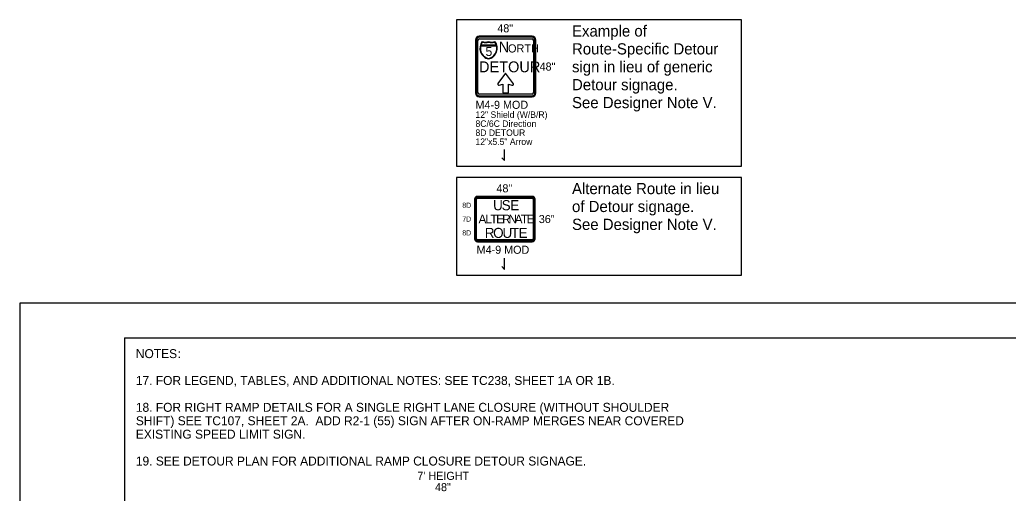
# Model space of a CAD drawing. Extents: x 99999 to 100116, y 99995 to 100013.
# Drawn here: x 100039.06 to 100047.9, y 100008.99 to 100013.22 of the extents above; entities that cross this region are included whole.
import ezdxf

# ---------------------------------------------------------------- set-up
doc = ezdxf.new("R2010")
doc.units = 0
for name, color, linetype in [('SH_GI_GeneralNotesBodyText', 7, 'Continuous'), ('SH_GI_PlotLimits', 7, 'Continuous'), ('SH_GI_SheetBorder', 7, 'Continuous'), ('TR_SN_ConstructionSigns', 7, 'Continuous'), ('TR_WZ_WorkZoneDetails', 7, 'Continuous')]:
    doc.layers.add(name, color=color, linetype=linetype)

msp = doc.modelspace()

# ---------------------------------------------------------------- linework, layer by layer
at = {"layer": 'SH_GI_PlotLimits'}
msp.add_lwpolyline([(100039.0625, 99999.6875), (100056.0625, 99999.6875), (100056.0625, 100010.6875), (100039.0625, 100010.6875)], close=True, dxfattribs=at)
at = {"layer": 'SH_GI_SheetBorder'}
for q in [(100040, 100000), (100055.75, 100010.375)]:
    msp.add_line((100040, 100010.375), q, dxfattribs=at)
at = {"layer": 'TR_SN_ConstructionSigns'}
for p, q in [((100043.1354, 100013.0373), (100043.1354, 100012.5648)), ((100043.1438, 100013.0373), (100043.1438, 100012.5648)), ((100043.1579, 100012.5648), (100043.1579, 100013.0373)), ((100043.6416, 100013.0711), (100043.1691, 100013.0711)), ((100043.6416, 100013.0626), (100043.1691, 100013.0626)), ((100043.1691, 100013.0486), (100043.6416, 100013.0486)), ((100043.6529, 100013.0373), (100043.6529, 100012.5648)), ((100043.6669, 100012.5648), (100043.6669, 100013.0373)), ((100043.6754, 100012.5648), (100043.6754, 100013.0373)), ((100043.3228, 100012.9875), (100043.1823, 100012.9875)), ((100043.1823, 100012.9875), (100043.3228, 100012.9875)), ((100043.1834, 100012.9912), (100043.3217, 100012.9912)), ((100043.3217, 100012.9912), (100043.1834, 100012.9912)), ((100043.6416, 100012.5536), (100043.1691, 100012.5536)), ((100043.1691, 100012.5395), (100043.6416, 100012.5395)), ((100043.1691, 100012.5311), (100043.6416, 100012.5311)), ((100043.6424, 100011.6405), (100043.153, 100011.6405)), ((100043.6424, 100011.6335), (100043.153, 100011.6335)), ((100043.153, 100011.6236), (100043.6424, 100011.6236)), ((100043.1277, 100011.6152), (100043.1277, 100011.2608)), ((100043.1347, 100011.6152), (100043.1347, 100011.2608)), ((100043.1446, 100011.2608), (100043.1446, 100011.6152)), ((100043.6508, 100011.6152), (100043.6508, 100011.2608)), ((100043.6607, 100011.2608), (100043.6607, 100011.6152)), ((100043.6677, 100011.2608), (100043.6677, 100011.6152)), ((100043.6424, 100011.2524), (100043.153, 100011.2524)), ((100043.153, 100011.2425), (100043.6424, 100011.2425)), ((100043.153, 100011.2355), (100043.6424, 100011.2355))]:
    msp.add_line(p, q, dxfattribs=at)
msp.add_lwpolyline([(100043.3367, 100012.6494), (100043.3356, 100012.6478), (100043.335, 100012.6461), (100043.3347, 100012.6441), (100043.3348, 100012.6424), (100043.335, 100012.6412), (100043.3356, 100012.6398), (100043.3373, 100012.6375), (100043.3386, 100012.6364), (100043.34, 100012.6355), (100043.3417, 100012.6348), (100043.3432, 100012.6345), (100043.3447, 100012.6343), (100043.3465, 100012.6343), (100043.3478, 100012.6346), (100043.3795, 100012.6424), (100043.3795, 100012.5671), (100043.4307, 100012.5671), (100043.4307, 100012.6429), (100043.4617, 100012.6337), (100043.4647, 100012.6331), (100043.4681, 100012.6334), (100043.4703, 100012.6342), (100043.4733, 100012.6362), (100043.4752, 100012.6389), (100043.476, 100012.6414), (100043.4761, 100012.6436), (100043.4754, 100012.6463), (100043.4746, 100012.6477), (100043.4051, 100012.7405), (100043.3367, 100012.6494)], dxfattribs=at)
for centre, radius, start, end in [((100043.1691, 100013.0373), 0.0337, 90, 180), ((100043.1691, 100013.0373), 0.0253, 90, 180), ((100043.1691, 100013.0373), 0.0113, 90, 180), ((100043.6416, 100013.0373), 0.0338, 360, 90), ((100043.6416, 100013.0373), 0.0253, 360, 90), ((100043.6416, 100013.0373), 0.0113, 360, 90), ((100043.2725, 100012.9642), 0.0973, 142.16169, 258.18105), ((100043.2715, 100012.9633), 0.0925, 164.85517, 258.18105), ((100043.2715, 100012.9633), 0.0925, 164.85517, 258.18105), ((100043.2715, 100012.9633), 0.0925, 142.16169, 162.48397), ((100043.2715, 100012.9633), 0.0925, 142.16169, 162.48397), ((100043.2245, 100013.1212), 0.1014, 253.48525, 286.04538), ((100043.2259, 100013.1124), 0.0964, 253.48525, 286.04538), ((100043.2259, 100013.1124), 0.0964, 253.48525, 286.04538), ((100043.2806, 100013.1212), 0.1014, 253.95462, 286.51475), ((100043.2792, 100013.1124), 0.0964, 253.95462, 286.51475), ((100043.2792, 100013.1124), 0.0964, 253.95462, 286.51475), ((100043.2325, 100012.9642), 0.0974, 281.90384, 37.84925), ((100043.2335, 100012.9633), 0.0925, 281.90384, 15.1558), ((100043.2335, 100012.9633), 0.0925, 281.90384, 15.1558), ((100043.2335, 100012.9633), 0.0925, 17.52691, 37.84925), ((100043.2335, 100012.9633), 0.0925, 17.52691, 37.84925), ((100043.1691, 100012.5648), 0.0338, 180, 270), ((100043.1691, 100012.5648), 0.0253, 180, 270), ((100043.1691, 100012.5648), 0.0113, 180, 270), ((100043.6416, 100012.5648), 0.0337, 270, 360), ((100043.6416, 100012.5648), 0.0253, 270, 0), ((100043.6416, 100012.5648), 0.0113, 270, 0), ((100043.153, 100011.6152), 0.0253, 90, 180), ((100043.153, 100011.6152), 0.0183, 90, 180), ((100043.153, 100011.6152), 0.00844, 90, 180), ((100043.6424, 100011.6152), 0.0253, 360, 90), ((100043.6424, 100011.6152), 0.0183, 360, 90), ((100043.6424, 100011.6152), 0.00844, 360, 90), ((100043.153, 100011.2608), 0.0253, 180, 270), ((100043.153, 100011.2608), 0.0183, 180, 270), ((100043.153, 100011.2608), 0.00844, 180, 270), ((100043.6424, 100011.2608), 0.0253, 270, 360), ((100043.6424, 100011.2608), 0.0183, 270, 0), ((100043.6424, 100011.2608), 0.00844, 270, 0)]:
    msp.add_arc(centre, radius, start, end, dxfattribs=at)
at = {"layer": 'TR_WZ_WorkZoneDetails'}
for p, q in [((100043.3963, 100011.9605), (100043.3963, 100012.0605)), ((100043.3713, 100011.9855), (100043.3963, 100011.9605)), ((100043.3963, 100010.9875), (100043.3963, 100011.0875)), ((100043.3713, 100011.0125), (100043.3963, 100010.9875))]:
    msp.add_line(p, q, dxfattribs=at)
for points in [[(100042.9666, 100011.9105), (100045.5143, 100011.9105), (100045.5143, 100013.2191), (100042.9666, 100013.2191)], [(100042.9666, 100010.9375), (100045.5143, 100010.9375), (100045.5143, 100011.8105), (100042.9666, 100011.8105)]]:
    msp.add_lwpolyline(points, close=True, dxfattribs=at)

# ---------------------------------------------------------------- texts
at = {"layer": 'SH_GI_GeneralNotesBodyText'}
for s, p in [('NOTES', (100040.1, 100010.195)), (':', (100040.4743, 100010.195)), ('17. FOR LEGEND, TABLES, AND ADDITIONAL NOTES: SEE TC238, SHEET 1A OR 1B.', (100040.1, 100009.955)), ('18. FOR RIGHT RAMP DETAILS FOR A SINGLE RIGHT LANE CLOSURE (WITHOUT SHOULDER ', (100040.1, 100009.715)), ('SHIFT) SEE TC107, SHEET 2A.  ADD R2-1 (55) SIGN AFTER ON-RAMP MERGES NEAR COVERED ', (100040.1, 100009.595)), ('EXISTING SPEED LIMIT SIGN.', (100040.1, 100009.475)), ('19. SEE DETOUR PLAN FOR ADDITIONAL RAMP CLOSURE DETOUR SIGNAGE.', (100040.1, 100009.235))]:
    msp.add_text(s, height=0.08, rotation=360, dxfattribs=at).set_placement(p)
at = {"layer": 'TR_SN_ConstructionSigns'}
for s, height, p in [('48"', 0.072, (100043.3306, 100013.1071)), ('5', 0.081, (100043.2253, 100012.8951)), ('N', 0.0972, (100043.3432, 100012.9267)), ('ORTH', 0.0729, (100043.4264, 100012.9267)), ('DETOUR', 0.0972, (100043.1668, 100012.7497)), ('48"', 0.072, (100043.7086, 100012.7651)), ('M4-9 MOD', 0.072, (100043.1354, 100012.4231)), ('12" Shield (W/B/R)', 0.0576, (100043.1354, 100012.3424)), ('8C/6C Direction', 0.0576, (100043.1354, 100012.2618)), ('8D DETOUR', 0.0576, (100043.1354, 100012.1811)), ('12"x5.5" Arrow', 0.0576, (100043.1354, 100012.1005)), ('48"', 0.072, (100043.323, 100011.6765)), ('36"', 0.072, (100043.7015, 100011.402)), ('M4-9 MOD', 0.072, (100043.1457, 100011.1275)), ("7' HEIGHT", 0.072, (100042.6156, 100009.1065)), ('48"', 0.072, (100042.774, 100009.0057))]:
    msp.add_text(s, height=height, rotation=360, dxfattribs=at).set_placement(p)
for s, height, p in [('8D', 0.045, (100043.018, 100011.5392)), ('U', 0.09, (100043.2933, 100011.5167)), ('S', 0.09, (100043.3698, 100011.5167)), ('E', 0.09, (100043.4463, 100011.5167)), ('7D', 0.045, (100043.018, 100011.4155)), ('A', 0.0787, (100043.1626, 100011.3986)), ('L', 0.0787, (100043.2241, 100011.3986)), ('T', 0.0787, (100043.269, 100011.3986)), ('E', 0.0787, (100043.3201, 100011.3986)), ('R', 0.0787, (100043.3737, 100011.3986)), ('N', 0.0787, (100043.4312, 100011.3986)), ('A', 0.0787, (100043.4863, 100011.3986)), ('T', 0.0787, (100043.5414, 100011.3986)), ('E', 0.0787, (100043.5926, 100011.3986)), ('R', 0.09, (100043.2186, 100011.2692)), ('O', 0.09, (100043.2933, 100011.2692)), ('U', 0.09, (100043.377, 100011.2692)), ('T', 0.09, (100043.4517, 100011.2692)), ('E', 0.09, (100043.521, 100011.2692)), ('8D', 0.045, (100043.018, 100011.2917))]:
    msp.add_text(s, height=height, dxfattribs=at).set_placement(p)
at = {"layer": 'TR_WZ_WorkZoneDetails'}
for s, p in [('Example of ', (100043.9983, 100013.0691)), ('Route-Specific Detour ', (100043.9983, 100012.9091)), ('sign in lieu of generic ', (100043.9983, 100012.7491)), ('Detour signage.', (100043.9983, 100012.5891)), ('See Designer Note V.', (100043.9983, 100012.4291)), ('Alternate Route in lieu ', (100043.9983, 100011.6605)), ('of Detour signage.', (100043.9983, 100011.5005)), ('See Designer Note V.', (100043.9983, 100011.3405))]:
    msp.add_text(s, height=0.1, dxfattribs=at).set_placement(p)

doc.saveas('drawing.dxf')
